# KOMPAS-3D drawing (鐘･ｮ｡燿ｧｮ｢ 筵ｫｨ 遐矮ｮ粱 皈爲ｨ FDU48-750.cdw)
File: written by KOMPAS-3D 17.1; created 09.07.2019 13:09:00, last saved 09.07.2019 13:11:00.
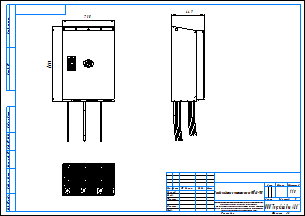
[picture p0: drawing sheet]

Sheet 1: A3, landscape

Title block, sheet 1: name: Преобразователи частоты серии FDU48-750; sheets: 1; sheet format: A3; stored path: \\adlc.lan\data\АДЛ_ПКД\3D-модели\Поставщики\Оборудование Emotron\Преобразователи частоты\Серия FDU 2.0\KOMPAS 2D\Преобразователи частоты серии FDU48-750.cdw

Views: Вид 1
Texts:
  user
  CONTINUOUS_RGB_0_0_0_THICK_0.18
  POLYLINE_STYLE_0.18_RGB_0_0_0
  Рама для чертежей
  Лит-Масса-Масштаб
  Материал-Предприятие
  Масштаб
  Изм.
  Лист
  № докум.
  Подп.
  Дата
  Лит.
  Разраб.
  Пров.
  Т.контр.
  Листов
  Внимание! Данный продукт является объектом авторского права ООО «Торговый Дом АДЛ».
  Запрещается изменение, копирование, распространение
  (в том числе путем копирования на другие сайты и ресурсы в Интернете)
  или любое иное использование информации и объектов без предварительного
  согласия правообладателя (ООО «Торговый Дом АДЛ»).
  Н.контр.
  Утв.
  ООО "Торговый дом АДЛ"
  Изменение
  Номер документа
  Подпись
  Обозначение документа
  Наименование изделия
  Масса изделия по ГОСТ 2.109-73
  Порядковый номер листа
  Общее количество листов в документе
  Характер работы, выполненной лицом, подписавшим документ
  Наименование или индекс предприятия, выпускающего документ
  Инв. № подл.
  Подп. и дата
  Взам. инв. №
  Инв. № дубл.
  Инвентарный номер подлинника по ГОСТ 2.501-68
  Подпись принявшего подлинник в отдел технической документации
  Инвентарный номер подлинника, взамен которого выпущен данный подлинник
  Инвентарный номер дубликата по ГОСТ 2.502-68
  Подпись принявшего дубликат в отдел технической документации
  Справ. №
  Перв. примен.
  Обозначение документа, взамен или на основании которого выпущен данный документ
  Обозначение документа, в котором впервые записан данный документ
  Подпись лица, копировавшего чертеж
  Обозначение формата листа
  !Рама для чертежа
Dimensions and other numbers on the sheet: 730; 1036; 449; 1:10; 1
